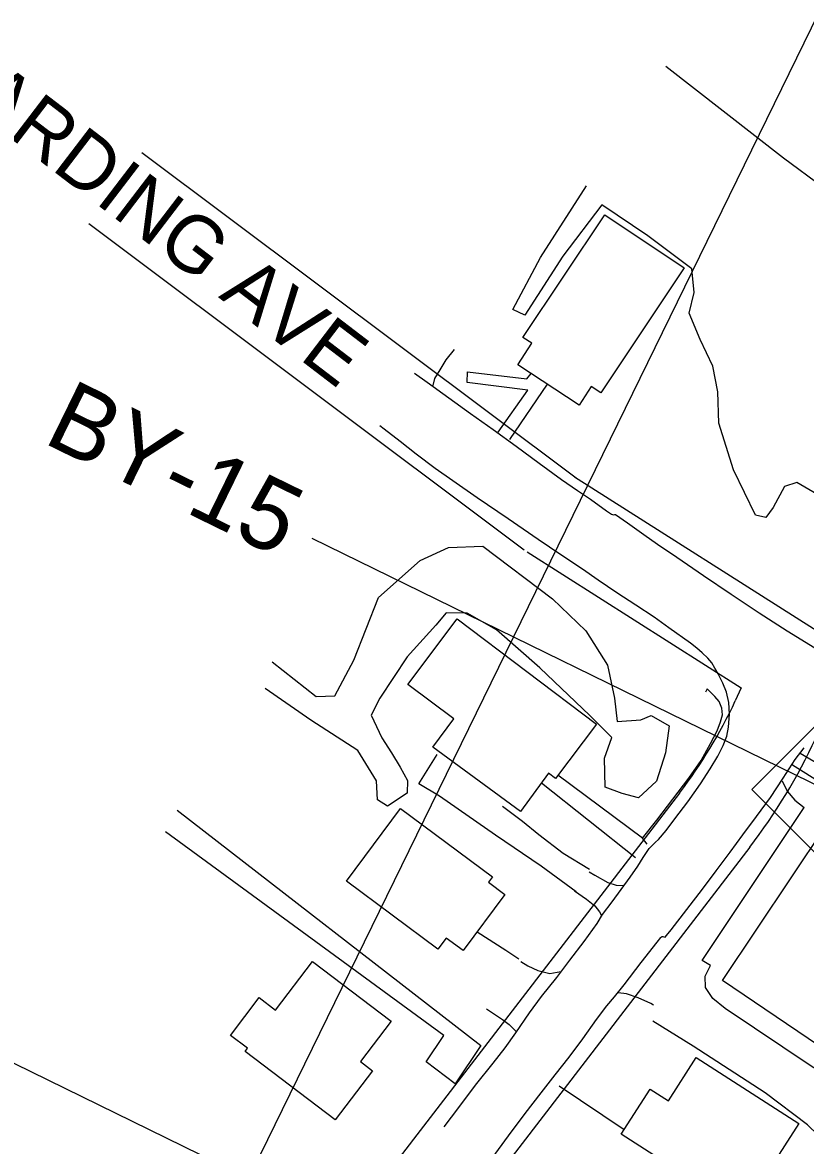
# Model space of a CAD drawing. Extents: x 1517485 to 1521905, y 636528 to 640355.
# Drawn here: x 1519953.2 to 1520173.9, y 637545.3 to 637861.7 of the extents above; entities that cross this region are included whole.
import ezdxf

# ---------------------------------------------------------------- set-up
doc = ezdxf.new("R2010")
doc.units = 0
for name, color, linetype in [('CTL Secondary Horizontal and Vertical Leader', 7, 'Continuous'), ('CTL Secondary Horizontal and Vertical Text', 7, 'Continuous'), ('Default', 7, 'Continuous'), ('Exist Building', 7, 'Continuous'), ('Exist Other Culture Area Outline', 7, 'Continuous'), ('Exist Right of Way Line', 7, 'Continuous'), ('Exist Roads EOP', 7, 'Continuous'), ('Exist Roads EOP Text', 7, 'Continuous'), ('Exist Roads Soil', 7, 'Continuous'), ('Exist Vegetation Woods Line', 7, 'Continuous'), ('Scratch_Level_3', 7, 'Continuous')]:
    doc.layers.add(name, color=color, linetype=linetype)

msp = doc.modelspace()

# ---------------------------------------------------------------- linework, layer by layer
at = {"layer": 'CTL Secondary Horizontal and Vertical Leader'}
msp.add_line((1520179.57, 637645.6), (1520034.8, 637716.4), dxfattribs=at)
at = {"layer": 'Default'}
msp.add_lwpolyline([(1520158.71, 637645.67), (1520179.67, 637666.63), (1520200.67, 637645.63), (1520179.71, 637624.67)], close=True, dxfattribs=at)
at = {"layer": 'Exist Building'}
for p, q in [((1520146.18, 637674.02), (1520145.66, 637673.06)), ((1520148.35, 637671.84), (1520146.18, 637674.02)), ((1520149.53, 637670.4), (1520148.35, 637671.84)), ((1520150.26, 637668.59), (1520149.53, 637670.4)), ((1520149.93, 637664.72), (1520150.45, 637666.64)), ((1520150.45, 637666.64), (1520150.26, 637668.59)), ((1520148.95, 637662.21), (1520149.93, 637664.72)), ((1520147.06, 637658.61), (1520148.95, 637662.21)), ((1520144.47, 637653.78), (1520147.06, 637658.61)), ((1520140.96, 637648.86), (1520144.47, 637653.78)), ((1520132, 637637.04), (1520140.96, 637648.86)), ((1520127.93, 637631.94), (1520132, 637637.04)), ((1520104.44, 637562.16), (1520122.73, 637549.83))]:
    msp.add_line(p, q, dxfattribs=at)
for points in [[(1520094.23, 637772.99), (1520117.35, 637807.58), (1520139.71, 637792.64), (1520116.16, 637757.4), (1520113.49, 637759.18), (1520110.05, 637753.96), (1520092.78, 637765.29), (1520096.79, 637771.39)], [(1520075.68, 637693.75), (1520114.96, 637664.04), (1520103.4, 637648.77), (1520101.46, 637650.21), (1520093.56, 637639.45), (1520068.88, 637657.6), (1520074.78, 637665.57), (1520061.8, 637675.26)], [(1520059.77, 637640.34), (1520085.68, 637621.06), (1520084.55, 637619.53), (1520089.18, 637616.08), (1520077.4, 637600.25), (1520072.63, 637603.8), (1520070.27, 637600.63), (1520044.5, 637619.81)], [(1520150.48, 637591.84), (1520179.54, 637635.19), (1520182.28, 637633.36), (1520186.68, 637639.92), (1520207.46, 637625.98), (1520203.34, 637619.84), (1520207, 637617.38), (1520204.14, 637613.12), (1520210.36, 637608.96), (1520206.9, 637603.81), (1520200.57, 637608.06), (1520186.98, 637587.84), (1520193.27, 637583.57), (1520183.63, 637569.36)], [(1520041.34, 637552.59), (1520015.93, 637571.88), (1520016.58, 637572.73), (1520011.8, 637576.37), (1520019.87, 637587.04), (1520024.55, 637583.48), (1520034.91, 637597.21), (1520057.14, 637580.43), (1520048.5, 637568.98), (1520051.88, 637566.43)], [(1520143.1, 637570.15), (1520171.98, 637551.59), (1520160.69, 637534.02), (1520155.58, 637537.3), (1520150.84, 637529.92), (1520121.89, 637548.53), (1520130.07, 637561.26), (1520135.25, 637557.94)]]:
    msp.add_lwpolyline(points, close=True, dxfattribs=at)
at = {"layer": 'Exist Other Culture Area Outline'}
for p, q in [((1520101.04, 637759.88), (1520090.42, 637744.25)), ((1520125.98, 637626.4), (1520099.43, 637647.44))]:
    msp.add_line(p, q, dxfattribs=at)
for points in [[(1520087.3, 637746.3), (1520095.6, 637758.14), (1520078.48, 637760.33), (1520078.62, 637763.28), (1520095.35, 637761.31), (1520096.52, 637762.84)], [(1520201.19, 637644.14), (1520198.7, 637640.38), (1520172.4, 637655.83)], [(1520194.65, 637634.58), (1520195.87, 637636.44), (1520170.25, 637652.47)], [(1520129.23, 637630.27), (1520127.93, 637631.94), (1520104.1, 637649.68)]]:
    msp.add_lwpolyline(points, dxfattribs=at)
at = {"layer": 'Exist Right of Way Line'}
for p, q in [((1519986.87, 637825.13), (1520109.61, 637733.16)), ((1519971.88, 637805.12), (1520094.62, 637713.16)), ((1520108.82, 637733.72), (1520259.42, 637638.14)), ((1520095.42, 637712.61), (1520155.79, 637674.3)), ((1520155.79, 637674.3), (1520154.08, 637670.6)), ((1520138.34, 637644.64), (1520012.02, 637480.39)), ((1520158.15, 637629.4), (1520031.83, 637465.15))]:
    msp.add_line(p, q, dxfattribs=at)
for radius in [137.5, 162.5]:
    msp.add_arc((1520029.34, 637728.47), radius, 322.4373, 335.1139, dxfattribs=at)
at = {"layer": 'Exist Roads EOP'}
for points in [[(1520063.66, 637762.93), (1520067.22, 637760.45), (1520073.37, 637755.98), (1520079.48, 637751.59), (1520085.86, 637747.03), (1520092.29, 637742.4), (1520098.84, 637737.59), (1520105.11, 637733.01), (1520109.64, 637729.93), (1520113.33, 637727.4), (1520117.83, 637724.17), (1520119.22, 637723.22), (1520119.49, 637723.09), (1520119.63, 637723.07), (1520120.06, 637723.11), (1520120.34, 637723.16), (1520123.67, 637720.79), (1520128.33, 637717.45), (1520132.21, 637714.8), (1520137.59, 637711.13), (1520145.15, 637705.94), (1520152.95, 637700.68), (1520160.85, 637695.46), (1520168.74, 637690.38), (1520176.53, 637685.54)], [(1520072.08, 637550.61), (1520076.22, 637556.08), (1520080.92, 637562.32), (1520085.83, 637568.55), (1520089.26, 637572.89), (1520092.24, 637577.11), (1520096.11, 637582.76), (1520099.5, 637587.34), (1520103.75, 637592.68), (1520107.5, 637597.55), (1520111.47, 637602.84), (1520115.12, 637607.9), (1520116.7, 637610.43), (1520119.35, 637614.04), (1520121.9, 637617.48), (1520124.44, 637620.92), (1520126.66, 637624.08), (1520128.13, 637626.5), (1520129.84, 637629.02), (1520130.44, 637629.73), (1520131.65, 637630.79), (1520132.47, 637631.58), (1520134.58, 637634.11), (1520137.09, 637637.38), (1520140.67, 637642.2), (1520144.31, 637647.27), (1520147.04, 637651.51), (1520149.14, 637655.05), (1520150.7, 637658), (1520151.67, 637660.67), (1520152.14, 637663.23), (1520152.44, 637666.86), (1520152.26, 637670.16), (1520151.6, 637673.05), (1520150.58, 637675.65), (1520149.24, 637678.24), (1520148.34, 637679.86), (1520147.48, 637681.29), (1520146.33, 637682.67), (1520144.78, 637684.15), (1520143.29, 637685.45), (1520141.43, 637686.85), (1520135.38, 637691.23), (1520131.26, 637694.16), (1520126.05, 637697.56), (1520120.73, 637701.05), (1520115.46, 637704.67), (1520111.01, 637707.68), (1520104.92, 637711.79), (1520098.58, 637716.09), (1520090.05, 637721.89), (1520081.34, 637727.83), (1520074.5, 637732.57), (1520069.51, 637736.1), (1520064.15, 637740.17), (1520059.63, 637743.68), (1520055.09, 637747.2), (1520053.9, 637748.09)], [(1520085.56, 637541.74), (1520090.18, 637548.04), (1520094.9, 637554.34), (1520099.42, 637560.22), (1520103.33, 637565.22), (1520107.23, 637570.25), (1520111.12, 637575.45), (1520114.98, 637580.86), (1520117.86, 637584.72), (1520120.01, 637587.27), (1520122.78, 637590.59), (1520127.6, 637596.9), (1520132.04, 637602.66), (1520133.14, 637603.99), (1520133.24, 637604.08), (1520133.33, 637604.14), (1520133.42, 637604.17), (1520133.52, 637604.19), (1520133.65, 637604.2), (1520133.93, 637604.18), (1520134.35, 637604.08), (1520134.73, 637604.48), (1520136.02, 637606.16), (1520140.48, 637611.89), (1520144.86, 637617.55), (1520148.73, 637622.74), (1520152.66, 637628.02), (1520156.21, 637632.84), (1520160.03, 637638), (1520164.02, 637643.4), (1520167.58, 637648.83), (1520170.99, 637654.13), (1520173.47, 637657.43)]]:
    msp.add_lwpolyline(points, dxfattribs=at)
at = {"layer": 'Exist Roads Soil'}
msp.add_line((1520144.75, 637597.45), (1520173.48, 637640.57), dxfattribs=at)
for points in [[(1520074.87, 637769.63), (1520072.48, 637766.74), (1520070.8, 637763.91), (1520069.35, 637761.45), (1520068.84, 637759.49)], [(1520070.74, 637643.73), (1520064.91, 637647.29), (1520070.09, 637655.54)], [(1520167.34, 637648.06), (1520168.69, 637645.21), (1520170.84, 637642.64), (1520173.48, 637640.57)], [(1520109.26, 637616.79), (1520099.37, 637624.03), (1520086.53, 637632.8), (1520070.74, 637643.73)], [(1520112.96, 637623.07), (1520105.58, 637627.6), (1520098.76, 637632.92), (1520094.16, 637636.67), (1520088.44, 637640.83)], [(1520112.89, 637622.5), (1520114.49, 637621.48), (1520118.21, 637619.42), (1520120.55, 637618.74), (1520122.61, 637618.58)], [(1520108.78, 637617.1), (1520112.2, 637614.74), (1520114.48, 637612.84), (1520115.85, 637611.23), (1520116.42, 637610.19)], [(1520081.38, 637605.59), (1520089.39, 637600.39), (1520093.06, 637597.97)], [(1520256.82, 637604.04), (1520255.46, 637599.9), (1520250.73, 637590.18), (1520245.75, 637579.93), (1520241.2, 637571.51), (1520237.56, 637565.28), (1520233.9, 637560.14), (1520229.2, 637555.8), (1520223.37, 637552.3), (1520214.29, 637549.22), (1520210.78, 637549.59), (1520203.29, 637551.6), (1520191.25, 637558.28), (1520175.78, 637567.48), (1520151.23, 637583.94), (1520147.78, 637586.77), (1520145.66, 637589.83), (1520145.64, 637593.03), (1520147.11, 637596.02), (1520144.75, 637597.45)], [(1520093.66, 637597.24), (1520095.58, 637595.99), (1520098.43, 637594.65), (1520101.84, 637593.81), (1520104.89, 637594.37)], [(1520131.01, 637584.92), (1520130.29, 637585.38), (1520126.71, 637587), (1520123.41, 637588.09), (1520121.09, 637588.41)], [(1520083.95, 637583.85), (1520088.52, 637580.84), (1520090.32, 637579.42), (1520092.3, 637577.45)], [(1520155.44, 637511.28), (1520163.69, 637511.68), (1520168.25, 637512.14), (1520173.44, 637513.86), (1520178.97, 637516.12), (1520183.84, 637518.8), (1520187.77, 637521.57), (1520188.83, 637523.16), (1520189.79, 637525.81), (1520189.51, 637530.29), (1520187.38, 637536.3), (1520184.55, 637540.94), (1520180.48, 637545.31), (1520174.42, 637551.21), (1520162.54, 637560.17), (1520142.19, 637573.35), (1520130.88, 637580.35)]]:
    msp.add_lwpolyline(points, dxfattribs=at)
at = {"layer": 'Exist Vegetation Woods Line'}
for points in [[(1520134.53, 637849.42), (1520167.67, 637823.64), (1520190.07, 637807.1), (1520209.8, 637788.5), (1520214.3, 637776.22)], [(1520182.2, 637725.83), (1520171.39, 637732.12), (1520167.99, 637730.97), (1520164.8, 637725.1), (1520162.7, 637722.31), (1520159.82, 637722.98), (1520153.59, 637735.74), (1520149.44, 637748.88), (1520149.21, 637757.67), (1520147.79, 637764.93), (1520144.19, 637772.43), (1520141.12, 637779.88), (1520142.46, 637785.69), (1520141.85, 637792.32), (1520129.45, 637801.64), (1520116.51, 637810.36), (1520105.5, 637795.92), (1520094.75, 637779.28), (1520091.39, 637780.91), (1520099.23, 637795.51), (1520112.2, 637815.73)], [(1520082.9, 637714.25), (1520102.55, 637699.39), (1520111.94, 637690.38), (1520118.06, 637680.69), (1520120.09, 637671.34), (1520120.76, 637664.77), (1520127.46, 637665.31), (1520130.41, 637666.5), (1520135.41, 637663.57), (1520134.44, 637655.94), (1520131.9, 637647.96), (1520126.82, 637643.33), (1520122.18, 637644.57), (1520117.38, 637646.27), (1520117.25, 637654.48), (1520119.29, 637660.27), (1520113.07, 637666.52), (1520099.02, 637679.95), (1520086.77, 637690.6), (1520078.49, 637695.35), (1520072.59, 637695.42), (1520069.74, 637691.92), (1520061.58, 637683.07), (1520053.95, 637671.4), (1520051.47, 637666.56), (1520054.47, 637660.18), (1520057.18, 637655.97), (1520059.63, 637651.98), (1520061.75, 637648.19), (1520061.57, 637644.62), (1520056.04, 637640.93), (1520053.22, 637642.75), (1520052.93, 637648.11), (1520047.7, 637656.65), (1520034.46, 637665.22), (1520021.64, 637674.11)], [(1520023.55, 637681.63), (1520035.98, 637671.88), (1520041.22, 637672), (1520046.62, 637682.12), (1520053.52, 637699.78), (1520065.27, 637710.12), (1520073.31, 637713.83), (1520082.9, 637714.25)], [(1519996.83, 637639.79), (1520082.36, 637573.49), (1520075.11, 637562.72), (1520066.93, 637568.9), (1520071.91, 637576.35), (1519993.48, 637633.74)]]:
    msp.add_lwpolyline(points, dxfattribs=at)
at = {"layer": 'Scratch_Level_3'}
for p in [(1520770.84, 639077.45), (1519081.21, 637993.84)]:
    msp.add_line(p, (1520017.02, 637536.16), dxfattribs=at)

# ---------------------------------------------------------------- texts
at = {"layer": 'CTL Secondary Horizontal and Vertical Text'}
msp.add_text('BY-15', height=20, rotation=333.9377, dxfattribs=at).set_placement((1519958.6, 637743.55))
at = {"layer": 'Exist Roads EOP Text'}
msp.add_text('S HARDING AVE', height=16, rotation=322.6115, dxfattribs=at).set_placement((1519909.06, 637860.2))

doc.saveas('drawing.dxf')
